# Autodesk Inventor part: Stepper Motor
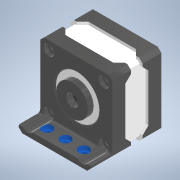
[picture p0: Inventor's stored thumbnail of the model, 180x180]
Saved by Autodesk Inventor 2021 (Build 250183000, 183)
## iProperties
Created: 2020-07
Part Number: Stepper Motor
Material: Brass, Soft Yellow, Welded
Document SubType Name: Modeling
Designer: Kafuko Martha
Density: 8.5 g/cm^3
Appearance: Smooth - Dark Gray
Author: Kafuko Martha
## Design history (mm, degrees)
sketch "Sketch1"
  geometry: L1 (22.5, -25)-(-22.5, -25); L2 (-25, -22.5)-(-25, 22.5); L3 (-22.5, 25)-(22.5, 25); L4 (25, 22.5)-(25, -22.5); L5 (-25, -22.5)-(-22.5, -25); L6 (22.5, -25)-(25, -22.5); L7 (22.5, 25)-(25, 22.5); L8 (-25, 22.5)-(-22.5, 25); 7 further points
  constraints: 16 end point, 8 point on line, 2 midpoint, 2 parallel, 2 perpendicular, 1 horizontal, 1 horizontal alignment, 1 vertical alignment
  dimensions: "d0" = 50 distance of point (25, -25) point (-25, -25); "d1" = 2.5 distance of L2.start point (-25, -25); "d2" = 2.5 distance of L1.end point (-25, -25) (= d1); "d3" = 2.5 distance of L1.start point (25, -25) (= d1); "d4" = 2.5 distance of L4.end point (25, -25) (= d3); "d5" = 2.5 distance of L3.end point (25, 25) (= d1); "d6" = 2.5 distance of L4.start point (25, 25) (= d5); "d7" = 2.5 distance of L2.end point (-25, 25) (= d1); "d8" = 2.5 distance of L3.start point (-25, 25) (= d1)
extrude "Extrusion1" new body sketch "Sketch1" distance "d9" = 34; taper "d10" = 0 deg
sketch "Sketch2"
  geometry: L1 (22.5, 25)-(-22.5, 25) reference; L2 (-22.5, 25)-(-25, 22.5) reference; L3 (-25, 22.5)-(-25, -22.5) reference; L4 (-25, -22.5)-(-22.5, -25) reference; L5 (-22.5, -25)-(22.5, -25) reference; L6 (22.5, -25)-(25, -22.5) reference; L7 (25, -22.5)-(25, 22.5) reference; L8 (25, 22.5)-(22.5, 25) reference; 5 further points
  constraints: 2 horizontal alignment, 2 vertical alignment
  dimensions: "d11" = 31 distance of point (15.5, 15.5) point (-15.5, 15.5); "d12" = 31 distance of point (-15.5, -15.5) point (-15.5, 15.5) (= d11); "d13" = 15.5 horizontal distance of point (-15.5, 15.5) point (0, 0) (= 0.5 x d11); "d14" = 15.5 horizontal distance of point (-15.5, 15.5) point (0, 0) (= 0.5 x d11)
hole "Hole1" sketch "Sketch2" at (-15.5, 15.5), (15.5, 15.5), (15.5, -15.5), (-15.5, -15.5) diameter "d15" = 3.45873; stored, may be unused: countersink angle "d19" = 90 deg, drill point angle "d21" = 118 deg; dims "d16" = 8, "d17" = 4.5, "d18" = 2, "d20" = 10.8
sketch "Sketch3"
  geometry: C1 r 15 at (0, 0); 1 further point
  constraints: 1 centre point, 1 coincident
  dimensions: "d22" = 30 diameter of C1
extrude "Extrusion2" cut sketch "Sketch3" distance "d23" = 1; taper "d24" = 0 deg
fillet "Fillet1" dims "d25" = 2
sketch "Sketch4"
  geometry: C1 r 15 at (0, 0) reference; C2 r 11 at (0, 0); C3 r 4 at (0, 0); 1 further point
  constraints: 2 centre point, 2 coincident
  dimensions: "d26" = 22 diameter of C2; "d27" = 8 diameter of C3
extrude "Extrusion3" join sketch "Sketch4" distance "d28" = 4; taper "d29" = 0 deg
fillet "Fillet2" dims "d33" = 0.25
sketch "Sketch7"
  geometry: L1 (6, 25)-(39, 25); L2 (0, 0)-(45, 0) reference; L3 (45, 0)-(45, 34) reference; L4 (0, 34)-(45, 34) reference; L5 (0, 0)-(0, 34) reference; L6 (6, 25)-(2, 21); L7 (2, 21)-(0, 21); L8 (39, 25)-(43, 21); L9 (43, 21)-(45, 21); L10 (45, 0)-(45, 34) reference; L11 (0, 21)-(0, 17); L12 (0, 0)-(0, 34) reference; L13 (0, 17)-(45, 17); L14 (45, 17)-(45, 21); 4 further points
  constraints: 16 end point, 4 point on line, 3 perpendicular, 2 horizontal, 2 midpoint, 1 vertical
  dimensions: "d37" = 17 distance between parallel lines of L13 L4; "d38" = 8 distance between parallel lines of L1 L13; "d39" = 4 distance between parallel lines of L7 L13; "d40" = 2 distance of L6.end L7.end; "d41" = 2 distance of L8.end L9.end (= d40)
extrude "Extrusion6" cut sketch "Sketch7" distance "d42" = 2; taper "d43" = 0 deg
sketch "Sketch8"
  geometry: L1 (-3.536, 0)-(0, 0) reference; L2 (0, 0)-(0, 34) reference; L3 (-3.536, 34)-(0, 34) reference; L4 (-3.536, 21)-(-3.536, 34) reference; L5 (-3.536, 17)-(-3.536, 21) reference; L6 (-3.536, 0)-(-3.536, 17) reference; L7 (-4.95, 21)-(-3.536, 21) reference; L8 (-3.536, 21)-(-3.536, 34) reference; L9 (-35.355, 34)-(-3.536, 34) reference; L10 (-35.355, 21)-(-35.355, 34) reference; L11 (-35.355, 21)-(-33.941, 21) reference; L12 (-33.941, 21)-(-31.113, 25) reference; L13 (-31.113, 25)-(-7.778, 25) reference; L14 (-7.778, 25)-(-4.95, 21) reference; L15 (-3.536, 17)-(-35.355, 17) reference; L16 (-35.355, 0)-(-35.355, 17) reference; L17 (-35.355, 0)-(-3.536, 0) reference; L18 (-3.536, 0)-(-3.536, 17) reference; L19 (-3.536, 21)-(0, 21); L20 (-3.536, 17)-(0, 17); L21 (0, 17)-(0, 21); L22 (-3.536, 21)-(-3.536, 17); 3 further points
  constraints: 8 end point, 1 horizontal, 1 midpoint, 1 parallel, 1 perpendicular, 1 point on line
extrude "Extrusion7" cut sketch "Sketch8" distance "d44" = 2; taper "d45" = 0 deg
sketch "Sketch9"
  geometry: L1 (0, 0)-(3.536, 0) reference; L2 (3.536, 0)-(3.536, 17) reference; L3 (3.536, 17)-(3.536, 21) reference; L4 (3.536, 21)-(3.536, 34) reference; L5 (0, 34)-(3.536, 34) reference; L6 (0, 0)-(0, 34) reference; L7 (35.355, 17)-(3.536, 17) reference; L8 (3.536, 0)-(3.536, 17) reference; L9 (3.536, 0)-(35.355, 0) reference; L10 (35.355, 0)-(35.355, 17) reference; L11 (33.941, 21)-(35.355, 21) reference; L12 (35.355, 21)-(35.355, 34) reference; L13 (3.536, 34)-(35.355, 34) reference; L14 (3.536, 21)-(3.536, 34) reference; L15 (3.536, 21)-(4.95, 21) reference; L16 (4.95, 21)-(7.778, 25) reference; L17 (7.778, 25)-(31.113, 25) reference; L18 (31.113, 25)-(33.941, 21) reference; L19 (3.536, 17)-(3.536, 21) reference; L20 (3.536, 17)-(0, 17); L21 (3.536, 21)-(0, 21); L22 (3.536, 17)-(3.536, 21); L23 (0, 21)-(0, 17); 1 further point
  constraints: 8 end point, 1 collinear, 1 midpoint, 1 parallel, 1 point on line
extrude "Extrusion8" cut sketch "Sketch9" distance "d46" = 2; taper "d47" = 0 deg
mirror "Mirror1"
sketch "Sketch10"
  geometry: L1 (0, 0)-(45, 0) reference; L2 (45, 0)-(45, 34) reference; L3 (0, 34)-(45, 34) reference; L4 (0, 21)-(0, 34) reference; L5 (0, 13)-(0, 21) reference; L6 (0, 0)-(0, 13) reference; L7 (0, 17)-(45, 17); L8 (45, 17)-(45, 21); L9 (45, 0)-(45, 34) reference; L10 (45, 21)-(43, 21); L11 (43, 21)-(39, 25); L12 (39, 25)-(6, 25); L13 (6, 25)-(2, 21); L14 (2, 21)-(0, 21); L15 (0, 17)-(0, 21); 3 further points
  constraints: 16 end point, 2 equal length, 2 midpoint, 2 perpendicular, 2 point on line, 1 horizontal, 1 parallel
  dimensions: "d48" = 8 distance between parallel lines of L12 L7; "d49" = 4 distance between parallel lines of L7 L14; "d50" = 4 distance between parallel lines of L7 L10 (= d49); "d51" = 2 distance of L13.end L14.end
extrude "Extrusion9" cut sketch "Sketch10" distance "d52" = 2; taper "d53" = 0 deg
mirror "Mirror2"
mirror "Mirror3"
mirror "Mirror4"
sketch "Sketch17"
  geometry: C1 r 2.25 at (15.5, -15.5) reference; C2 r 2.5 at (15.5, -15.5); C3 r 2.25 at (-15.5, -15.5) reference; C4 r 2.5 at (-15.5, -15.5); C5 r 1.729 at (-15.5, 15.5) reference; C6 r 2.5 at (-15.5, 15.5); C7 r 2.25 at (15.5, 15.5) reference; C8 r 2.5 at (15.5, 15.5); 1 further point
  constraints: 4 centre point, 4 coincident
  dimensions: "d83" = 5 diameter of C2; "d84" = 5 diameter of C4; "d85" = 5 diameter of C6; "d86" = 5 diameter of C8
extrude "Extrusion12" join sketch "Sketch17" stored distance "d87" = 10; taper "d88" = 0 deg
sketch "Sketch13"
  geometry: C1 r 2.5 at (0, 0); C2 r 4 at (0, 0) reference
  constraints: 1 centre point, 1 coincident
  dimensions: "d75" = 5 diameter of C1
extrude "Extrusion11" cut sketch "Sketch13" distance "d72" = 6; taper "d73" = 0 deg
sketch "Sketch11"
  geometry: L1 (22.5, 25)-(-22.5, 25) reference; L2 (25, 22.5)-(22.5, 25) reference; L3 (-22.5, 25)-(-25, 22.5) reference; L4 (22.5, 25)-(25, 22.5) reference; L5 (25, 22.5)-(-25, 22.5); L6 (25, 22.5)-(22.5, 25) reference; L7 (25, 21)-(-25, 21); L8 (-22.5, 25)-(-25, 22.5) reference; L9 (25, 22.5)-(25, 21); L10 (25, -22.5)-(25, 22.5) reference; L11 (-25, 22.5)-(-22.5, 25) reference; L12 (-25, 22.5)-(-25, 21); L13 (-25, 22.5)-(-25, -22.5) reference; 3 further points
  constraints: 8 end point, 2 point on line, 1 horizontal
  dimensions: "d99" = 4 distance between parallel lines of L7 L1
extrude "Extrusion10" join sketch "Sketch11" distance "d55" = 15; taper "d56" = 0 deg
sketch "Sketch20"
  geometry: L1 (0, -15)-(0, 0) reference; L2 (50, -15)-(50, 0) reference; L3 (0, 0)-(50, 0) reference; 4 further points
  constraints: 2 horizontal alignment
  dimensions: "d111" = 12.7 distance of point (25, -7.5) point (37.7, -7.5); "d112" = 12.7 distance of point (12.3, -7.5) point (25, -7.5); "d114" = 50 distance between parallel lines of L1 L2 (derived); "d115" = 25 distance from line of point (25, -7.5) L2 (derived); "d116" = 15 distance of L1.start L1.end (derived); "d117" = 7.5 distance from line of point (25, -7.5) L3 (derived)
hole "Hole5" sketch "Sketch20" at (37.7, -7.5), (25, -7.5), (12.3, -7.5) diameter "d118" = 4; stored, may be unused: countersink angle "d122" = 90 deg, drill point angle "d124" = 118 deg; dims "d119" = 6, "d120" = 7.25, "d121" = 2.8, "d123" = 8
sketch "Sketch18"
  geometry: C1 r 1.626 at (-19.05, -19.05) reference; C2 r 1.626 at (19.05, -19.05) reference; C3 r 1.626 at (-19.05, 19.05) reference; C4 r 1.626 at (19.05, 19.05) reference; 5 further points
  constraints: 4 coincident
hole "Hole4" sketch "Sketch18" at (19.05, -19.05), (-19.05, -19.05), (-19.05, 19.05), (19.05, 19.05) diameter "d89" = 4; stored, may be unused: countersink angle "d93" = 90 deg, drill point angle "d95" = 118 deg; dims "d90" = 8, "d91" = 7.25, "d92" = 2.8, "d94" = 8
sketch "Sketch21"
  geometry: C1 r 3.625 at (0, 0) reference; C2 r 2 at (0, 0) reference; C3 r 3.625 at (-38.1, 0) reference; C4 r 2 at (-38.1, 0) reference; 1 further point
extrude "Extrusion14" cut sketch "Sketch21" extent not by distance; stored distance "d125" = 0; taper "d126" = 0 deg
fillet "Fillet4" dims "d130" = 2
fillet "Fillet5" dims "d131" = 1
body "Solid1"
node "Projected Loop1"
node "Projected Loop2"
node "Projected Loop4"
node "Projected Loop5"
node "Projected Loop6"
node "Projected Loop7"
node "Projected Loop8"
node "Projected Loop9"
node "Projected Loop10"
node "Projected Loop11"
node "Reference3"
node "Reference4"
node "Reference5"
node "Reference6"
node "Projected Loop13"
node "Projected Loop14"
